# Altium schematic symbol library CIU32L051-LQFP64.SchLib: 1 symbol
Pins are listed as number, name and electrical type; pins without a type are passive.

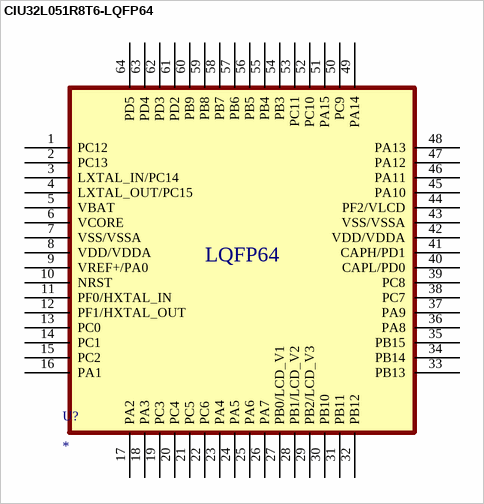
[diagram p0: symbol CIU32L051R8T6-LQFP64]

## CIU32L051R8T6-LQFP64
designator U?
footprint CIU32L051-LQFP_64N (pin间距小于0.2，pin2pin不能阻焊)
pins: 1 PC12, 2 PC13, 3 LXTAL_IN/PC14, 4 LXTAL_OUT/PC15, 5 VBAT, 6 VCORE, 7 VSS/VSSA, 8 VDD/VDDA, 9 VREF+/PA0, 10 NRST, 11 PF0/HXTAL_IN, 12 PF1/HXTAL_OUT, 13 PC0, 14 PC1, 15 PC2, 16 PA1, 17 PA2, 18 PA3, 19 PC3, 20 PC4, 21 PC5, 22 PC6, 23 PA4, 24 PA5, 25 PA6, 26 PA7, 27 PB0/LCD_V1, 28 PB1/LCD_V2, 29 PB2/LCD_V3, 30 PB10, 31 PB11, 32 PB12, 33 PB13, 34 PB14, 35 PB15, 36 PA8, 37 PA9, 38 PC7, 39 PC8, 40 CAPL/PD0, 41 CAPH/PD1, 42 VDD/VDDA, 43 VSS/VSSA, 44 PF2/VLCD, 45 PA10, 46 PA11, 47 PA12, 48 PA13, 49 PA14, 50 PC9, 51 PA15, 52 PC10, 53 PC11, 54 PB3, 55 PB4, 56 PB5, 57 PB6, 58 PB7, 59 PB8, 60 PB9, 61 PD2, 62 PD3, 63 PD4, 64 PD5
